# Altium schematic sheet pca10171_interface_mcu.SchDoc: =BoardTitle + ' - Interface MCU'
size A3; Organization: Nordic Semiconductor; DocumentNumber: 3; SheetNumber: 3; SheetTotal: 10; CompanyName: Nordic Semiconductor; DocumentSize: A3
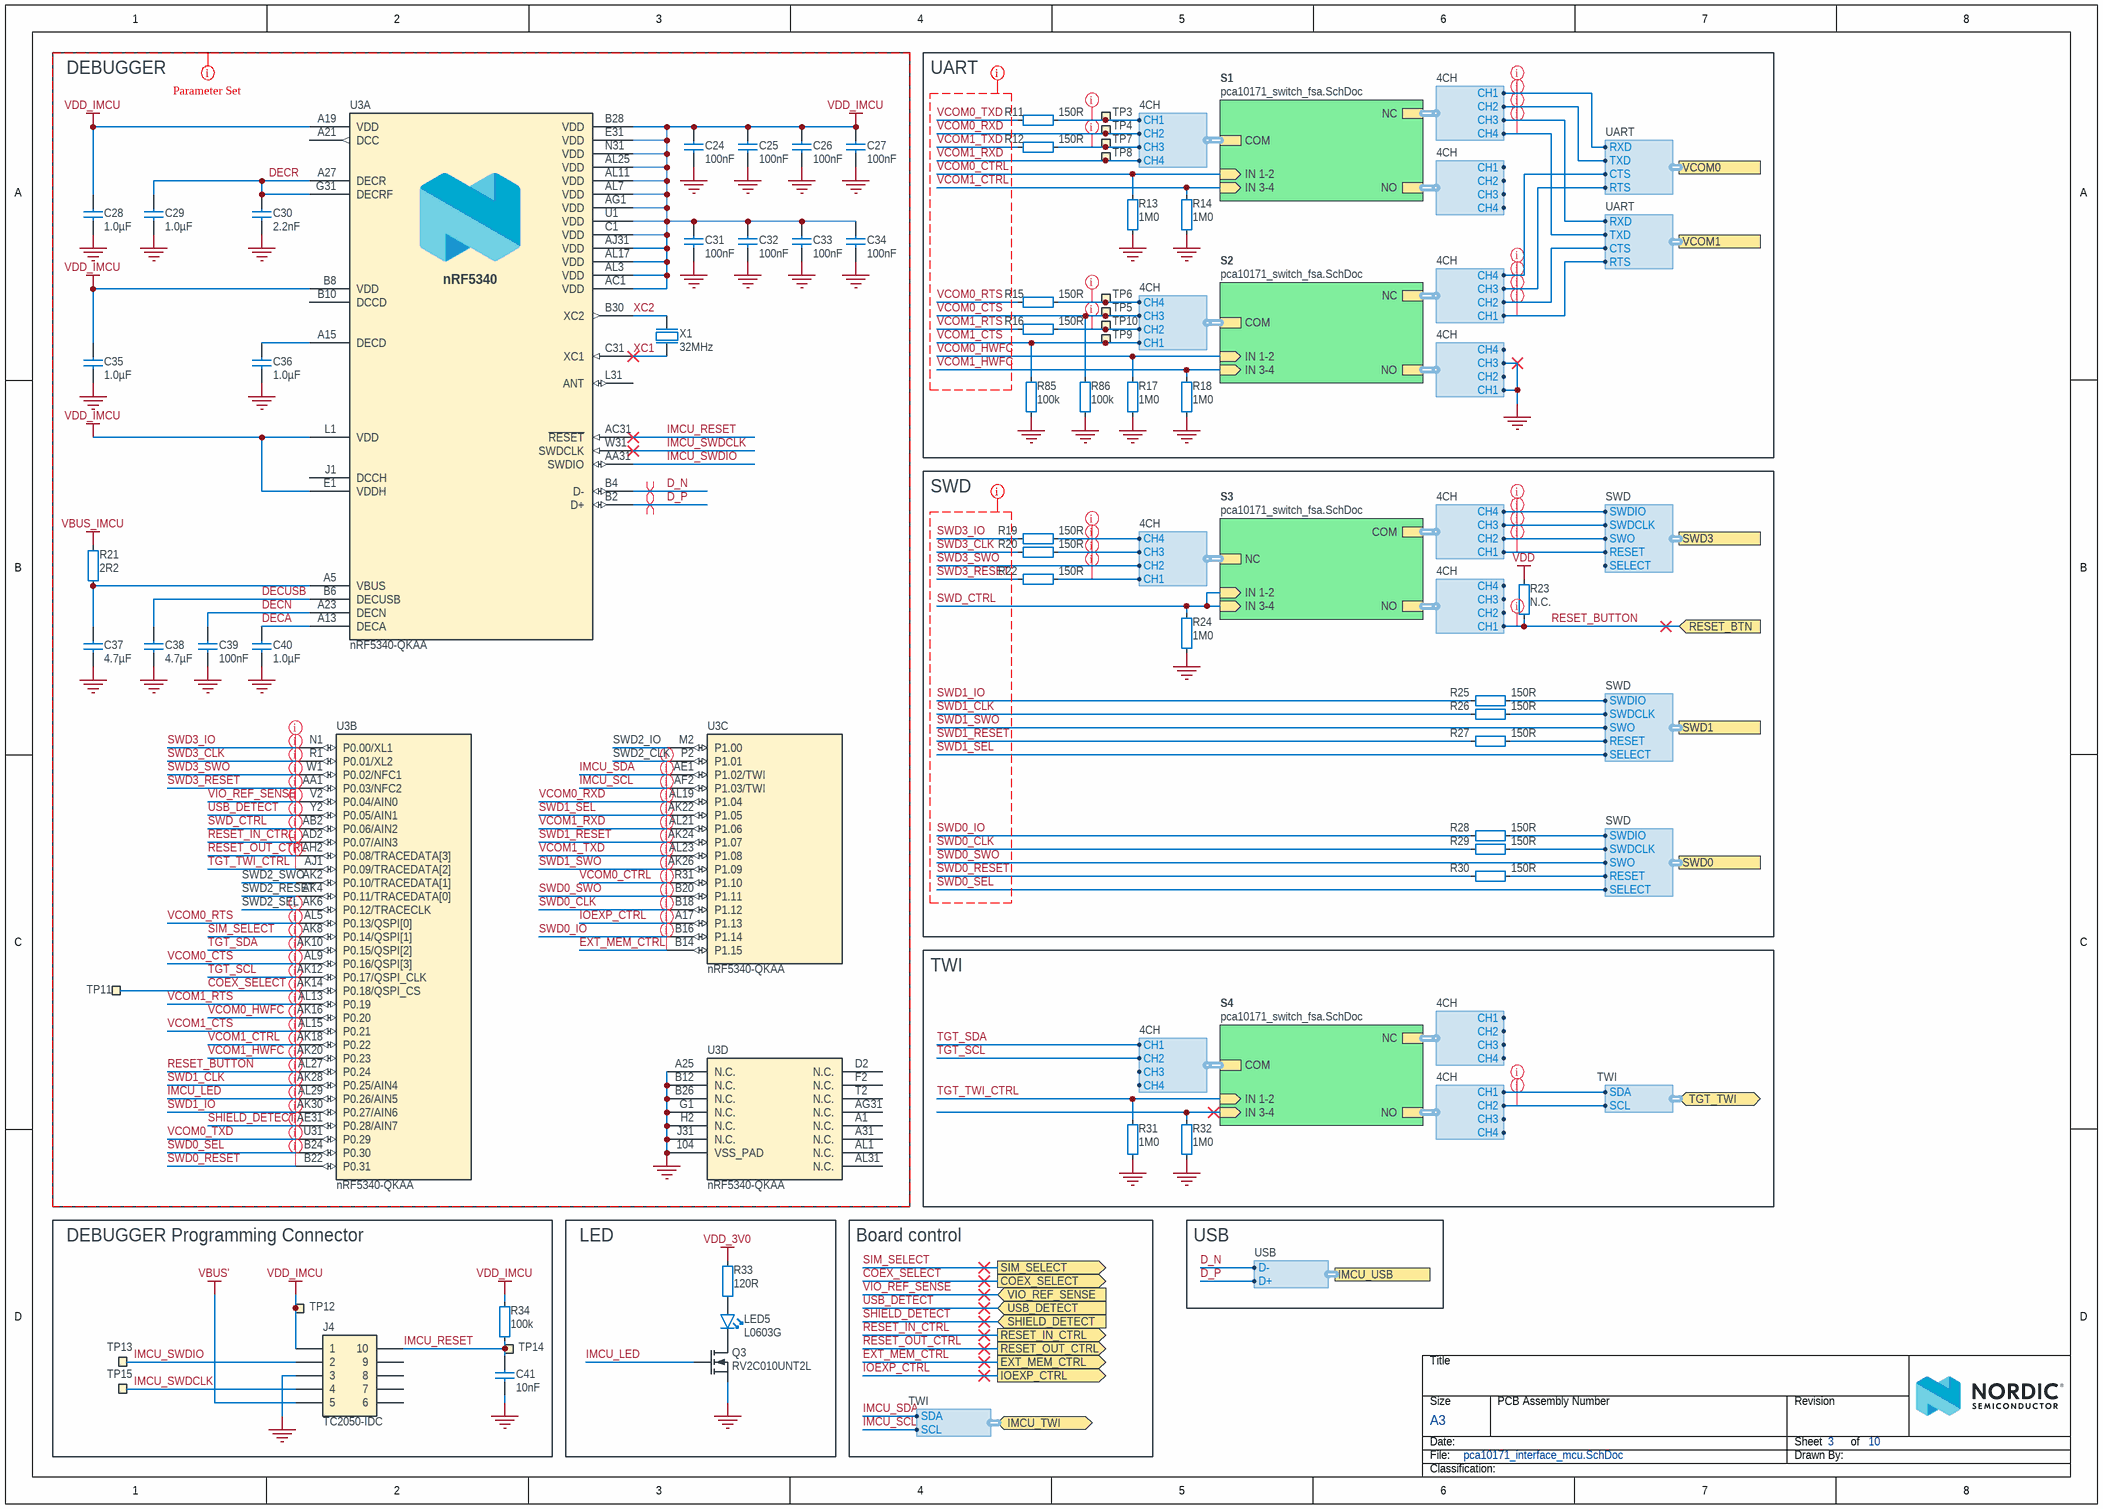
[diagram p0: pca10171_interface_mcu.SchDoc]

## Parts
C24  100nF  [CAPC0603X03L_C]
C25  100nF  [CAPC0603X03L_C]
C26  100nF  [CAPC0603X03L_C]
C27  100nF  [CAPC0603X03L_C]
C28  1.0µF  [CAPC1005X04L]
C29  1.0µF  [CAPC1005X04L]
C30  2.2nF  [CAPC0603X03L_C]
C31  100nF  [CAPC0603X03L_C]
C32  100nF  [CAPC0603X03L_C]
C33  100nF  [CAPC0603X03L_C]
C34  100nF  [CAPC0603X03L_C]
C35  1.0µF  [CAPC1005X04L]
C36  1.0µF  [CAPC1005X04L]
C37  4.7µF  [CAPC1608X06L]
C38  4.7µF  [CAPC1608X06L]
C39  100nF  [CAPC0603X03L_C]
C40  1.0µF  [CAPC1005X04L]
C41  10nF  [CAPC0603X03L_C]
J4  TC2050-IDC  [TC2050-IDC-NLFP]  (no BOM)
LED5  L0603G  [LED_0603_G]
Q3  RV2C010UNT2L  [DFN65P100X40-3L]
R11  150R  [RESC0603X03L_C]
R12  150R  [RESC0603X03L_C]
R13  1M0  [RESC0603X03L_C]
R14  1M0  [RESC0603X03L_C]
R15  150R  [RESC0603X03L_C]
R16  150R  [RESC0603X03L_C]
R17  1M0  [RESC0603X03L_C]
R18  1M0  [RESC0603X03L_C]
R19  150R  [RESC0603X03L_C]
R20  150R  [RESC0603X03L_C]
R21  2R2  [RESC0603X03L_C]
R22  150R  [RESC0603X03L_C]
R23  N.C.  [RESC0603X03L_C_NC]
R24  1M0  [RESC0603X03L_C]
R25  150R  [RESC0603X03L_C]
R26  150R  [RESC0603X03L_C]
R27  150R  [RESC0603X03L_C]
R28  150R  [RESC0603X03L_C]
R29  150R  [RESC0603X03L_C]
R30  150R  [RESC0603X03L_C]
R31  1M0  [RESC0603X03L_C]
R32  1M0  [RESC0603X03L_C]
R33  120R  [RESC0603X03L_C]
R34  100k  [RESC0603X03L_C]
R85  100k  [RESC0603X03L_C]
R86  100k  [RESC0603X03L_C]
TP3  Ø1.5mm,SMD  [TP_SMD_D1.5mm]  (value not drawn)  (no BOM)
TP4  Ø1.5mm,SMD  [TP_SMD_D1.5mm]  (value not drawn)  (no BOM)
TP5  Ø1.5mm,SMD  [TP_SMD_D1.5mm]  (value not drawn)  (no BOM)
TP6  Ø1.5mm,SMD  [TP_SMD_D1.5mm]  (value not drawn)  (no BOM)
TP7  Ø1.5mm,SMD  [TP_SMD_D1.5mm]  (value not drawn)  (no BOM)
TP8  Ø1.5mm,SMD  [TP_SMD_D1.5mm]  (value not drawn)  (no BOM)
TP9  Ø1.5mm,SMD  [TP_SMD_D1.5mm]  (value not drawn)  (no BOM)
TP10  Ø1.5mm,SMD  [TP_SMD_D1.5mm]  (value not drawn)  (no BOM)
TP11  Ø1.5mm,SMD  [TP_SMD_D1.5mm]  (value not drawn)  (no BOM)
TP12  Ø1.5mm,SMD  [TP_SMD_D1.5mm]  (value not drawn)  (no BOM)
TP13  Ø1.5mm,SMD  [TP_SMD_D1.5mm]  (value not drawn)  (no BOM)
TP14  Ø1.5mm,SMD  [TP_SMD_D1.5mm]  (value not drawn)  (no BOM)
TP15  Ø1.5mm,SMD  [TP_SMD_D1.5mm]  (value not drawn)  (no BOM)
U3  nRF5340-QKAA  [AQFN40P700X700X85_HS-99N]  (parts A,B,C,D of 4)
X1  32MHz  [BT-XTAL_2016]

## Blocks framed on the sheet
DEBUGGER: C24-C40 R21 TP11 U3 X1
UART: R11-R18 R85 R86 TP3-TP10
SWD: R19 R20 R22-R30
TWI: R31 R32
DEBUGGER Programming Connector: C41 J4 R34 TP12-TP15
LED: LED5 Q3 R33

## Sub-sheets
S1 = pca10171_switch_fsa.SchDoc: IN 1-2 (in), COM (harness 4CH), NC (harness 4CH), NO (harness 4CH), IN 3-4 (in)
S2 = pca10171_switch_fsa.SchDoc: IN 1-2 (in), COM (harness 4CH), NC (harness 4CH), NO (harness 4CH), IN 3-4 (in)
S3 = pca10171_switch_fsa.SchDoc: IN 1-2 (in), COM (harness 4CH), NC (harness 4CH), NO (harness 4CH), IN 3-4 (in)
S4 = pca10171_switch_fsa.SchDoc: IN 1-2 (in), COM (harness 4CH), NC (harness 4CH), NO (harness 4CH), IN 3-4 (in)

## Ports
COEX_SELECT (out), EXT_MEM_CTRL (out), IMCU_TWI (bidir, harness TWI), IMCU_USB (harness USB), IOEXP_CTRL (out), RESET_BTN (in), RESET_IN_CTRL (out), RESET_OUT_CTRL (out), SHIELD_DETECT (in), SIM_SELECT (out), SWD0 (harness SWD), SWD1 (harness SWD), SWD3 (harness SWD), TGT_TWI (bidir, harness TWI), USB_DETECT (in), VCOM0 (harness UART), VCOM1 (harness UART), VIO_REF_SENSE (in)

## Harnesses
TWI: SCL, SDA
SWD: SWDIO, SWDCLK, SWO, RESET, SELECT
USB: D+, D-
4CH: CH1, CH2, CH3, CH4
UART: RTS, CTS, RXD, TXD

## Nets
GND: C24.1 C25.1 C26.2 C27.1 C28.2 C29.1 C30.2 C31.1 C32.1 C33.1 C34.2 C35.1 C36.1 C37.2 C38.2 C39.2 C40.1 C41.1 J4.3 Q3.2(S) R13.2 R14.1 R17.2 R18.1 R24.1 R31.2 R32.1 R85.2 R86.2 U3.104(VSS_PAD) U3.A25(N.C.) U3.B12(N.C.) U3.B26(N.C.) U3.G1(N.C.) U3.H2(N.C.) U3.J31(N.C.) X1.2(GND) X1.4(GND) ; sheet S2/NO.CH1, sheet S2/NO.CH3
VBUS': J4.5
VBUS_IMCU: R21.1
VDD: R23.2
VDD_3V0: R33.2
VDD_IMCU: C24.2 C25.2 C26.1 C27.2 C28.1 C31.2 C32.2 C33.2 C34.1 C35.2 J4.1 R34.2 TP12.1 U3.A19(VDD) U3.AC1(VDD) U3.AG1(VDD) U3.AJ31(VDD) U3.AL3(VDD) U3.AL7(VDD) U3.AL11(VDD) U3.AL17(VDD) U3.AL25(VDD) U3.B8(VDD) U3.B28(VDD) U3.C1(VDD) U3.E1(VDDH) U3.E31(VDD) U3.L1(VDD) U3.N31(VDD) U3.U1(VDD)
COEX_SELECT: TP11.1 U3.AK14(P0.18/QSPI_CS) ; port COEX_SELECT
D_N: U3.B4(D-) ; port IMCU_USB.D-
D_P: U3.B2(D+) ; port IMCU_USB.D+
DECA: C40.2 U3.A13(DECA)
DECN: C39.1 U3.A23(DECN)
DECR: C29.2 C30.1 U3.A27(DECR) U3.G31(DECRF)
DECUSB: C38.1 U3.B6(DECUSB)
EXT_MEM_CTRL: U3.B14(P1.15) ; port EXT_MEM_CTRL
IMCU_LED: Q3.1(G) U3.AL29(P0.26/AIN5)
IMCU_RESET: C41.2 J4.10 R34.1 TP14.1 U3.AC31(~{RESET})
IMCU_SCL: U3.AF2(P1.03/TWI) ; port IMCU_TWI.SCL
IMCU_SDA: U3.AE1(P1.02/TWI) ; port IMCU_TWI.SDA
IMCU_SWDCLK: J4.4 TP15.1 U3.W31(SWDCLK)
IMCU_SWDIO: J4.2 TP13.1 U3.AA31(SWDIO)
IOEXP_CTRL: U3.A17(P1.13) ; port IOEXP_CTRL
RESET_BUTTON: R23.1 U3.AL27(P0.24) ; port RESET_BTN, sheet S3/NO.CH1
RESET_IN_CTRL: U3.AD2(P0.07/AIN3) ; port RESET_IN_CTRL
RESET_OUT_CTRL: U3.AH2(P0.08/TRACEDATA[3]) ; port RESET_OUT_CTRL
SHIELD_DETECT: U3.AE31(P0.28/AIN7) ; port SHIELD_DETECT
SIM_SELECT: U3.AK8(P0.14/QSPI[1]) ; port SIM_SELECT
SWD0_CLK: R29.1 U3.B18(P1.12)
SWD0_IO: R28.1 U3.B16(P1.14)
SWD0_RESET: R30.1 U3.B22(P0.31)
SWD0_SEL: U3.B24(P0.30) ; port SWD0.SELECT
SWD0_SWO: U3.B20(P1.11) ; port SWD0.SWO
SWD1_CLK: R26.1 U3.AK28(P0.25/AIN4)
SWD1_IO: R25.1 U3.AK30(P0.27/AIN6)
SWD1_RESET: R27.1 U3.AK24(P1.07)
SWD1_SEL: U3.AK22(P1.05) ; port SWD1.SELECT
SWD1_SWO: U3.AK26(P1.09) ; port SWD1.SWO
SWD3_CLK: R20.1 U3.R1(P0.01/XL2)
SWD3_IO: R19.1 U3.N1(P0.00/XL1)
SWD3_RESET: R22.1 U3.AA1(P0.03/NFC2)
SWD3_SWO: U3.W1(P0.02/NFC1) ; sheet S3/NC.CH2
SWD_CTRL: R24.2 U3.AB2(P0.06/AIN2) ; sheet S3/IN 1-2, sheet S3/IN 3-4
TGT_SCL: U3.AK12(P0.17/QSPI_CLK) ; sheet S4/COM.CH2
TGT_SDA: U3.AK10(P0.15/QSPI[2]) ; sheet S4/COM.CH1
TGT_TWI_CTRL: R31.1 U3.AJ1(P0.09/TRACEDATA[2]) ; sheet S4/IN 1-2
USB_DETECT: U3.Y2(P0.05/AIN1) ; port USB_DETECT
VCOM0_CTRL: R13.1 U3.R31(P1.10) ; sheet S1/IN 1-2
VCOM0_CTS: R86.1 TP5.1 U3.AL9(P0.16/QSPI[3]) ; sheet S2/COM.CH3
VCOM0_HWFC: R17.1 U3.AK16(P0.20) ; sheet S2/IN 1-2
VCOM0_RTS: R15.1 U3.AL5(P0.13/QSPI[0])
VCOM0_RXD: TP4.1 U3.AL19(P1.04) ; sheet S1/COM.CH2
VCOM0_TXD: R11.1 U3.U31(P0.29)
VCOM1_CTRL: R14.2 U3.AK18(P0.22) ; sheet S1/IN 3-4
VCOM1_CTS: R85.1 TP9.1 U3.AL15(P0.21) ; sheet S2/COM.CH1
VCOM1_HWFC: R18.2 U3.AK20(P0.23) ; sheet S2/IN 3-4
VCOM1_RTS: R16.1 U3.AL13(P0.19)
VCOM1_RXD: TP8.1 U3.AL21(P1.06) ; sheet S1/COM.CH4
VCOM1_TXD: R12.1 U3.AL23(P1.08)
VIO_REF_SENSE: U3.V2(P0.04/AIN0) ; port VIO_REF_SENSE
XC1: U3.C31(XC1) X1.1(inp)
XC2: U3.B30(XC2) X1.3(out)
NetC36_2: C36.2 U3.A15(DECD)
NetC37_1: C37.1 R21.2 U3.A5(VBUS)
NetLED5_1: LED5.1(C) Q3.3(D)
NetLED5_2: LED5.2(A) R33.1
NetR11_2: R11.2 TP3.1 ; sheet S1/COM.CH1
NetR12_2: R12.2 TP7.1 ; sheet S1/COM.CH3
NetR15_2: R15.2 TP6.1 ; sheet S2/COM.CH4
NetR16_2: R16.2 TP10.1 ; sheet S2/COM.CH2
NetR19_2: R19.2 ; sheet S3/NC.CH4
NetR20_2: R20.2 ; sheet S3/NC.CH3
NetR22_2: R22.2 ; sheet S3/NC.CH1
NetR25_2: R25.2 ; port SWD1.SWDIO
NetR26_2: R26.2 ; port SWD1.SWDCLK
NetR27_2: R27.2 ; port SWD1.RESET
NetR28_2: R28.2 ; port SWD0.SWDIO
NetR29_2: R29.2 ; port SWD0.SWDCLK
NetR30_2: R30.2 ; port SWD0.RESET
NetR32_2: R32.2 ; sheet S4/IN 3-4
(unnamed): sheet S1/NC.CH1, port VCOM0.RXD
(unnamed): sheet S1/NC.CH2, port VCOM0.TXD  [a separate net that carries the same name]
(unnamed): sheet S1/NC.CH3, port VCOM1.RXD  [a separate net that carries the same name]
(unnamed): sheet S1/NC.CH4, port VCOM1.TXD  [a separate net that carries the same name]
(unnamed): port VCOM0.RTS, sheet S2/NC.CH3  [a separate net that carries the same name]
(unnamed): port VCOM0.CTS, sheet S2/NC.CH4  [a separate net that carries the same name]
(unnamed): port VCOM1.RTS, sheet S2/NC.CH1  [a separate net that carries the same name]
(unnamed): port VCOM1.CTS, sheet S2/NC.CH2  [a separate net that carries the same name]
(unnamed): sheet S3/COM.CH1, port SWD3.RESET  [a separate net that carries the same name]
(unnamed): sheet S3/COM.CH2, port SWD3.SWO  [a separate net that carries the same name]
(unnamed): sheet S3/COM.CH3, port SWD3.SWDCLK  [a separate net that carries the same name]
(unnamed): sheet S3/COM.CH4, port SWD3.SWDIO  [a separate net that carries the same name]
(unnamed): port TGT_TWI.SCL, sheet S4/NO.CH2  [a separate net that carries the same name]
(unnamed): port TGT_TWI.SDA, sheet S4/NO.CH1  [a separate net that carries the same name]

Not connected (* = marked no-connect by the designer): J4 6 7 8 9; U3 A1(N.C.) A21(DCC) A31(N.C.) AG31(N.C.) AK2(P0.10/TRACEDATA[1]) AK4(P0.11/TRACEDATA[0]) AK6(P0.12/TRACECLK) AL1(N.C.) AL31(N.C.) B10(DCCD) D2(N.C.) F2(N.C.) J1(DCCH) L31(ANT) M2(P1.00) P2(P1.01) T2(N.C.)

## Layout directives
differential pair: D_N, D_P
net class GPIO: (no net found under the mark), COEX_SELECT, EXT_MEM_CTRL, IMCU_LED, IMCU_SCL, IMCU_SDA, IOEXP_CTRL, NetR11_2, NetR12_2, NetR15_2, NetR16_2, NetR19_2, NetR20_2, NetR22_2, RESET_BUTTON, RESET_IN_CTRL, RESET_OUT_CTRL, SHIELD_DETECT, SIM_SELECT, SWD0_CLK, SWD0_IO, SWD0_RESET, SWD0_SEL, SWD0_SWO, SWD1_CLK, SWD1_IO, SWD1_RESET, SWD1_SEL, SWD1_SWO, SWD3_CLK, SWD3_IO, SWD3_RESET, SWD3_SWO, SWD_CTRL, TGT_SCL, TGT_SDA, TGT_TWI_CTRL, USB_DETECT, VCOM0_CTRL, VCOM0_CTS, VCOM0_HWFC, VCOM0_RTS, VCOM0_RXD, VCOM0_TXD, VCOM1_CTRL, VCOM1_CTS, VCOM1_HWFC, VCOM1_RTS, VCOM1_RXD, VCOM1_TXD, VIO_REF_SENSE
CompClassName: IMCU: COEX_SELECT, D_N, D_P, DECA, DECN, DECR, DECUSB, EXT_MEM_CTRL, GND, IMCU_LED, IMCU_RESET, IMCU_SCL, IMCU_SDA, IMCU_SWDCLK, IMCU_SWDIO, IOEXP_CTRL, RESET_BUTTON, RESET_IN_CTRL, RESET_OUT_CTRL, SHIELD_DETECT, SIM_SELECT, SWD0_CLK, SWD0_IO, SWD0_RESET, SWD0_SEL, SWD0_SWO, SWD1_CLK, SWD1_IO, SWD1_RESET, SWD1_SEL, SWD1_SWO, SWD3_CLK, SWD3_IO, SWD3_RESET, SWD3_SWO, SWD_CTRL, TGT_SCL, TGT_SDA, TGT_TWI_CTRL, USB_DETECT, VBUS_IMCU, VCOM0_CTRL, VCOM0_CTS, VCOM0_HWFC, VCOM0_RTS, VCOM0_RXD, VCOM0_TXD, VCOM1_CTRL, VCOM1_CTS, VCOM1_HWFC, VCOM1_RTS, VCOM1_RXD, VCOM1_TXD, VDD_IMCU, VIO_REF_SENSE, XC1, XC2
net class VCOM: VCOM0_CTRL, VCOM0_CTS, VCOM0_HWFC, VCOM0_RTS, VCOM0_RXD, VCOM0_TXD, VCOM1_CTRL, VCOM1_CTS, VCOM1_HWFC, VCOM1_RTS, VCOM1_RXD, VCOM1_TXD
net class SWD: SWD0_CLK, SWD0_IO, SWD0_RESET, SWD0_SEL, SWD0_SWO, SWD1_CLK, SWD1_IO, SWD1_RESET, SWD1_SEL, SWD1_SWO, SWD3_CLK, SWD3_IO, SWD3_RESET, SWD3_SWO, SWD_CTRL

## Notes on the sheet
- (near U3) SWD2_IO
- (near U3) SWD2_CLK
- (near U3) SWD2_SWO
- (near U3) SWD2_RESET
- (near U3) SWD2_SEL
- Board control
- USB

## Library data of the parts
C24-C27 C31-C33 = C0201-100n: Capacitor, X5R, ±10%; Manufacturer: N.A.; Part number IPS: 00000001248, 00000002505; Part number Norautron: 262071862; Part number NEMS: 100200078; Note: 16V; Pad Count: 2; Component Status: Active
C28 C29 C35 C36 C40 = C0402-1µ0-10V-X5R: Capacitor, Ceramic, X5R, ±10%, 10V; Manufacturer: N.A.; Part number NEMS: 100200482; Pad Count: 2; Component Status: Active
C30 = C0201-2n2: Capacitor, X7R, ±10%, 10V; Manufacturer: N.A.; Part number IPS: 00000001778; Part number Norautron: 26470002; Part number NEMS: 100200060; Pad Count: 2; Component Status: Active
C34 C39 = C0201-100n: Capacitor, X5R, ±10%; Manufacturer: N.A.; Part number IPS: 00000001248, 00000002505; Part number Norautron: 262071862; Part number NEMS: 100200078; Pad Count: 2; Note: 16V; Component Status: Active
C37 C38 = C0603-4µ7-10V-X5R: Capacitor, Ceramic, X5R, ±10%, 10V; Manufacturer: N.A.; Part number Norautron: 262081761; Part number NEMS: 100200479; Pad Count: 2; Component Status: Active
C41 = C0201-10n: Capacitor, X7R, ±10%; Manufacturer: N.A.; Part number IPS: 00000003480; Part number Norautron: 26621779; Part number NEMS: 100200067; Note: 10V; Pad Count: 2; Component Status: Active
J4 = TC2050-IDC-NLFP: CBL PLUG-OF-NAILS 10-PIN; Manufacturer: Tag-Connect LLC; Part number NEMS: 100500463; Artikkelnr Noca: N.A.; Pad Count: 10; Component Status: Active; System: Connector
LED5 = VS 25C7M5: LED, Green, 0603, 573nm, Vf=2.0V, 24mcd, - 40 to +85°C; Manufacturer: Victory Electronics; Part number IPS: 00000001274, 00000009961; Part number Norautron: 26313411; Part number NEMS: 101400097; Note: N.A.; Artikkelnr Noca: 13019193; Pad Count: 2; Component Status: Active
Q3 = RV2C010UNT2L: N-Channel MOSFET, 20V, 1A, 470mOhm, 400mW; Manufacturer: Rohm Semiconductor; Part number IPS: 00000009976; Part number Norautron: 26320026; Part number NEMS: 101300132; Note: N.A.; Artikkelnr Noca: 35010020; Pad Count: 3; Component Status: Active
R11 R12 R15 R16 R19 R20 R22 R25-R30 = R0201-150: Resistor, ±1%, 0.05W; Manufacturer: N.A.; Part number IPS: 00000001420; Part number NEMS: 100100029; Note: Chip Res 1%; Pad Count: 2; Component Status: Active
R13 R14 R17 R18 R24 R31 R32 = R0201-1M0: Resistor, ±1%, 0.05W; Manufacturer: N.A.; Part number IPS: 00000001418; Part number Norautron: 26107108; Part number NEMS: 100100093; Note: Chip Res 1%; Pad Count: 2; Component Status: Active
R21 = R0201-2R2: Resistor, ±1%, 0.05W; Manufacturer: N.A.; Part number Norautron: 26470029; Part number NEMS: 100100006; Pad Count: 2; Note: Chip Res 1%; Component Status: Active
R23 = R0201-N.C.: Not mounted; Manufacturer: N.A.; Part number NEMS: 100100107; Note: Chip Res; Assembly: Not mounted; Pad Count: 2; Component Status: Active
R33 = R0201-120: Resistor, ±1%, 0.05W; Manufacturer: N.A.; Part number IPS: 00000000880; Part number Norautron: 26107076; Part number NEMS: 100100028; Note: Chip Res 1%; Pad Count: 2; Component Status: Active
R34 R85 R86 = R0201-100k: Resistor, ±1%, 0.05W; Manufacturer: N.A.; Part number IPS: 00000001419; Part number Norautron: 26108487; Part number NEMS: 100100080; Note: Chip Res 1%; Pad Count: 2; Component Status: Active
TP3-TP15 = TP_SMD_Ø1.5MM: 1.5mm circular SMD testpad; Manufacturer: Nordic Semiconductor; Manufacturer Part Number: N.A.; Part number NEMS: 100500477; Pad Count: 1; Component Status: Active
U3 = nRF5340-QKAAD0: Multi-protocol Bluetooth Low Energy, IEEE 802.15.4, ANT and 2.4GHz proprietary system-on-chip; Manufacturer: Nordic Semiconductor; Part number Norautron: NOD26470035; Part number NEMS: 102000216; Pad Count: 98; Note: N.A.; Component Status: Active
X1 = XTAL_SMD2016_32MHz_8pF_Kyocera: XTAL SMD 2016, 32MHz, Cl=8pF, Tot: ±40ppm; Manufacturer Part Number: CX2016DB32000D0WZRC1; Part number IPS: 00000007827; Part number Norautron: 26511136; Part number NEMS: 101600039; Pad Count: 4; Note: XTAL SMD 32.000MHz; Artikkelnr Noca: 22010022; Component Status: Active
